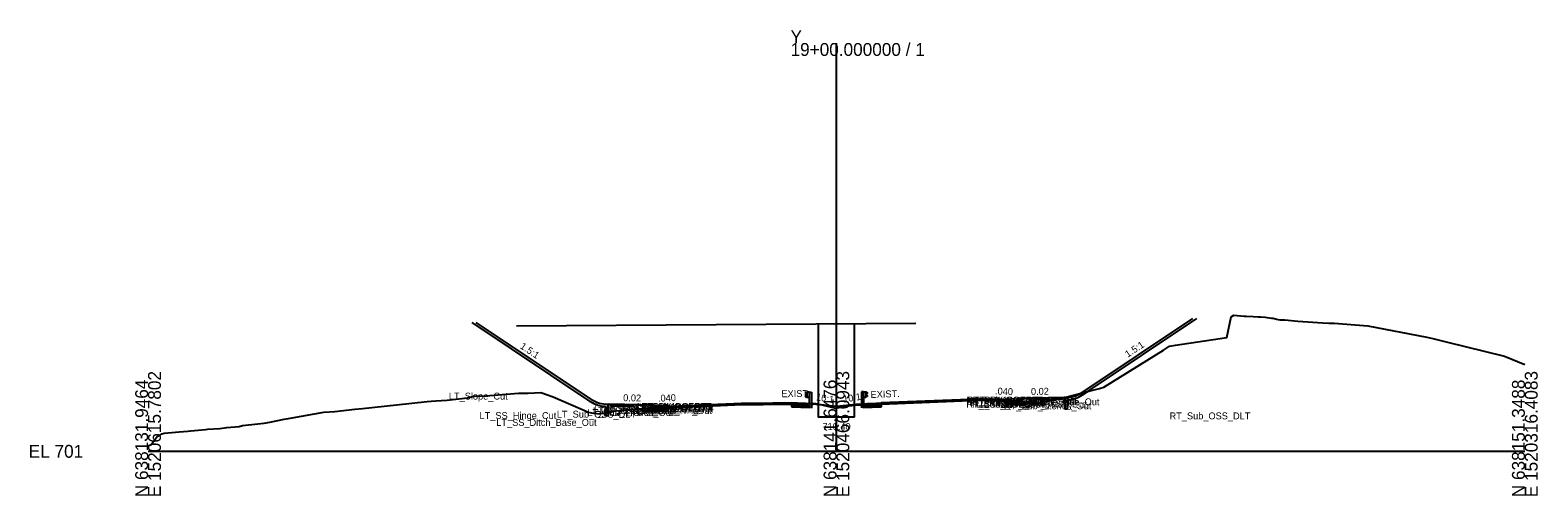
# Model space of a CAD drawing. Extents: x -26 to 303, y -10 to 5039.
# Drawn here: x -25.7 to 302.8, y 2490.3 to 2591.7 of the extents above; entities that cross this region are included whole.
import ezdxf

# ---------------------------------------------------------------- set-up
doc = ezdxf.new("R2010")
doc.units = 0
for name, color, linetype in [('Default', 7, 'Continuous'), ('Exist Cross Section Cell', 7, 'Continuous'), ('Exist XS Center Line Elevation Label', 7, 'Continuous'), ('Exist XS Ground Line', 7, 'Continuous'), ('Prop CMT Bridge Metal Rail', 7, 'Continuous'), ('Prop CMT Pvmt Course 1', 7, 'Continuous'), ('Prop CMT Pvmt Course 2', 7, 'Continuous'), ('Prop CMT Pvmt Course 3', 7, 'Continuous'), ('Prop CMT Pvmt Surface Shoulder', 7, 'Continuous'), ('Prop CMT Shld Paved Course 1', 7, 'Continuous'), ('Prop CMT Shld Paved Course 2', 7, 'Continuous'), ('Prop CMT Shld Paved Course 3', 7, 'Continuous'), ('Prop CMT Slope Grass', 7, 'Continuous'), ('Prop CMT Subgrade Earthwork', 7, 'Continuous'), ('Prop Conc 4in Sidewalk', 7, 'Continuous'), ('Prop XS Earthwork Shape', 7, 'Continuous'), ('Prop XS SE Text', 7, 'Continuous'), ('Prop XS Side Slope Text', 7, 'Continuous'), ('Scratch_Level_0', 7, 'Continuous'), ('Scratch_Level_1', 7, 'Continuous'), ('Typical Curb CELL', 7, 'Continuous'), ('Typical Guardrail CELL', 7, 'Continuous'), ('Typical Shoulder Slope Information CELL', 7, 'Continuous')]:
    doc.layers.add(name, color=color, linetype=linetype)

# ---------------------------------------------------------------- blocks, each defined once
blk = doc.blocks.new('2_6 CURB RIGHT')
at = {"layer": 'Typical Curb CELL'}
for p, q in [((0, -0.58), (0, 0)), ((0, 0), (1.75, -0.07)), ((2, 0.17), (2, 0.18)), ((2.5, 0.42), (2.24, 0.42)), ((2.31, 0.08), (2.33, -0.01)), ((2.46, 0.04), (2.31, 0.08)), ((2.33, -0.01), (2.46, 0.04)), ((2.5, -0.58), (2.5, 0.42)), ((2.5, -0.58), (0, -0.58)), ((0.26, -0.34), (0.35, -0.22)), ((0.38, -0.34), (0.26, -0.34)), ((0.35, -0.22), (0.38, -0.34)), ((1.03, -0.39), (1.09, -0.28)), ((1.19, -0.36), (1.03, -0.39)), ((1.09, -0.28), (1.19, -0.36)), ((1.51, -0.34), (1.6, -0.22)), ((1.63, -0.34), (1.51, -0.34)), ((1.6, -0.22), (1.63, -0.34)), ((2.27, -0.39), (2.34, -0.28)), ((2.44, -0.36), (2.27, -0.39)), ((2.34, -0.28), (2.44, -0.36))]:
    blk.add_line(p, q, dxfattribs=at)
for centre in [(2.27, 0.34), (2.43, 0.12), (2.49, 0.31), (0.01, -0.55), (0.02, -0.25), (0.03, -0.15), (0.07, -0.39), (0.09, -0.18), (0.17, -0.34), (0.2, -0.06), (0.22, -0.58), (0.3, -0.14), (0.34, -0.04), (0.38, -0.51), (0.49, -0.1), (0.52, -0.21), (0.59, -0.53), (0.67, -0.29), (0.69, -0.12), (0.7, -0.45), (0.71, -0.07), (0.76, -0.56), (0.79, -0.26), (0.93, -0.5), (0.97, -0.1), (1.09, -0.15), (1.11, -0.54), (1.26, -0.55), (1.27, -0.25), (1.28, -0.15), (1.32, -0.39), (1.34, -0.18), (1.42, -0.34), (1.45, -0.1), (1.47, -0.58), (1.54, -0.14), (1.63, -0.51), (1.74, -0.1), (1.77, -0.21), (1.84, -0.53), (1.92, -0.29), (1.94, -0.12), (1.95, -0.45), (1.96, -0.07), (2.01, -0.56), (2.04, -0.26), (2.18, -0.5), (2.22, -0.1), (2.34, -0.15), (2.35, -0.54)]:
    blk.add_circle(centre, 0.00802, dxfattribs=at)
for centre, start, end in [((1.76, 0.17), 267.6155, 0), ((2.24, 0.18), 90, 180)]:
    blk.add_arc(centre, 0.24, start, end, dxfattribs=at)

msp = doc.modelspace()

# ---------------------------------------------------------------- linework, layer by layer
at = {"layer": 'Exist Cross Section Cell'}
for p, q in [((150, 2500), (150, 2588.88)), ((0, 2500), (150, 2500)), ((150, 2500), (300, 2500))]:
    msp.add_line(p, q, dxfattribs=at)
at = {"layer": 'Exist XS Ground Line'}
msp.add_lwpolyline([(0, 2501.16), (0.7, 2501.5), (2.01, 2503.24), (2.64, 2503.53), (3.02, 2503.8), (3.52, 2503.95), (5.99, 2504.17), (6.79, 2504.21), (8.64, 2504.35), (9.32, 2504.44), (12.49, 2504.74), (12.98, 2504.8), (15.63, 2504.94), (17.13, 2505.15), (19.83, 2505.39), (20.59, 2505.59), (23.92, 2505.97), (25.3, 2506.15), (26.56, 2506.33), (29.68, 2507.03), (31.37, 2507.27), (38.28, 2508.49), (40.73, 2508.7), (45.04, 2509.14), (46.76, 2509.29), (54.1, 2510.12), (60.8, 2510.87), (61.71, 2510.9), (62.71, 2510.98), (65.17, 2511.14), (69.63, 2511.67), (70.88, 2511.98), (73.59, 2512.09), (80.7, 2512.68), (82.85, 2512.64), (85.59, 2512.79), (88.24, 2511.86), (95.95, 2508.51), (96.61, 2508.37), (98.4, 2508.14), (101.94, 2508.81), (107.02, 2509.27), (110.46, 2509.52), (110.77, 2509.54), (112.13, 2509.61), (112.95, 2509.67), (114.15, 2509.75), (114.51, 2509.75), (116.45, 2509.85), (117.15, 2509.88), (119.77, 2510.01), (121.55, 2510.11), (122.16, 2510.14), (124.76, 2510.26), (125.89, 2510.33), (127.14, 2510.35), (129.14, 2510.38), (129.63, 2510.39), (131.5, 2510.41), (132.16, 2510.42), (132.89, 2510.43), (134.66, 2510.46), (135.53, 2510.47), (137.06, 2510.48), (138.08, 2510.51), (141.53, 2510.46), (145.46, 2510.38), (147.5, 2509.99), (149.82, 2509.37), (152.24, 2509.8), (154.42, 2510.08), (158.72, 2510.33), (162.26, 2510.58), (162.88, 2510.59), (164.76, 2510.65), (165.06, 2510.66), (167.26, 2510.74), (169.18, 2510.81), (169.76, 2510.83), (170.42, 2510.86), (172.26, 2510.92), (173.17, 2510.96), (174.1, 2511), (174.75, 2511), (175.76, 2511.02), (177.25, 2511.06), (178.44, 2511.08), (179.75, 2511.11), (180.9, 2511.13), (182.25, 2511.15), (183.76, 2511.17), (184.74, 2511.18), (185.05, 2511.17), (185.41, 2511.16), (185.87, 2511.15), (187.3, 2511.05), (190.09, 2510.87), (192.06, 2510.44), (192.93, 2510.26), (196.43, 2511.01), (199.73, 2511.7), (205.01, 2513.12), (207.33, 2513.65), (208.26, 2513.99), (221.25, 2521.99), (222.61, 2522.89), (223.91, 2523.09), (235.08, 2524.77), (236.02, 2529.27), (236.59, 2529.63), (238.88, 2529.39), (239.31, 2529.43), (240.83, 2529.34), (241.89, 2529.3), (242.43, 2529.3), (243.43, 2529.23), (244.81, 2529.02), (245.15, 2528.97), (245.87, 2528.78), (246.64, 2528.63), (247.69, 2528.61), (250.57, 2528.31), (256.02, 2527.96), (257.27, 2527.91), (258.49, 2527.86), (265.8, 2527.35), (278.68, 2524.84), (279.96, 2524.57), (282.83, 2523.85), (295.54, 2520.74), (300, 2518.91)], dxfattribs=at)
at = {"layer": 'Prop CMT Bridge Metal Rail'}
for p, q in [((96.36, 2510.86), (70.63, 2528.02)), ((96.64, 2511.28), (71.52, 2528.02)), ((167.28, 2527.82), (80.27, 2527.26)), ((153.92, 2507.41), (153.92, 2527.73)), ((203.32, 2512.66), (227.65, 2528.88)), ((204.83, 2513.07), (228.56, 2528.89)), ((100.24, 2510.27), (100.24, 2507.77)), ((100.25, 2510.27), (100.25, 2507.77)), ((199.75, 2511.68), (199.65, 2511.68)), ((199.75, 2511.68), (199.75, 2509.18)), ((200.25, 2511.18), (200.25, 2509.18)), ((203.64, 2512.28), (204.83, 2513.07)), ((99.75, 2509.77), (99.75, 2507.77)), ((99.75, 2507.77), (100.24, 2507.77)), ((200.25, 2509.18), (199.75, 2509.18))]:
    msp.add_line(p, q, dxfattribs=at)
msp.add_lwpolyline([(153.92, 2507.41), (146.08, 2507.41), (146.08, 2527.68)], dxfattribs=at)
for centre, radius, start, end in [((99.98, 2516.26), 6.5, 236.1329, 267.9819), ((99.98, 2516.26), 6, 236.1329, 272.5897), ((200.02, 2517.68), 6, 267.4103, 303.3375), ((200.02, 2517.68), 6.5, 272.0181, 303.8602)]:
    msp.add_arc(centre, radius, start, end, dxfattribs=at)
at = {"layer": 'Prop CMT Pvmt Course 1'}
for points in [[(140.25, 2510.29), (140.25, 2510.54)], [(159.73, 2510.29), (159.73, 2510.54)], [(186.74, 2510.87), (186.74, 2511.12)], [(113.26, 2509.45), (113.26, 2509.7)]]:
    msp.add_lwpolyline(points, dxfattribs=at)
at = {"layer": 'Prop CMT Pvmt Course 2'}
for points in [[(140.25, 2510.04), (140.25, 2510.29)], [(159.73, 2510.04), (159.73, 2510.29)]]:
    msp.add_lwpolyline(points, dxfattribs=at)
at = {"layer": 'Prop CMT Pvmt Course 3'}
for points in [[(140.25, 2509.66), (140.25, 2510.04)], [(159.73, 2509.66), (159.73, 2510.04)], [(140.26, 2509.66), (140.25, 2509.66)], [(159.72, 2509.66), (159.73, 2509.66)]]:
    msp.add_lwpolyline(points, dxfattribs=at)
at = {"layer": 'Prop CMT Pvmt Surface Shoulder'}
msp.add_line((140.25, 2510.54), (143.24, 2510.43), dxfattribs=at)
for points in [[(127.86, 2510.36), (112.25, 2509.66)], [(140.25, 2510.54), (127.86, 2510.36)], [(156.74, 2510.43), (180.9, 2511.35)], [(180.9, 2511.35), (187.75, 2511.07)]]:
    msp.add_lwpolyline(points, dxfattribs=at)
at = {"layer": 'Prop CMT Shld Paved Course 1'}
for p, q in [((143.51, 2510.16), (143.24, 2510.43)), ((156.47, 2510.16), (156.74, 2510.43)), ((159.73, 2510.29), (180.98, 2511.1))]:
    msp.add_line(p, q, dxfattribs=at)
for points in [[(112.25, 2509.41), (127.87, 2510.11)], [(127.87, 2510.11), (140.25, 2510.29)], [(187.75, 2510.82), (180.98, 2511.1)], [(187.75, 2510.82), (186.74, 2510.87)], [(112.25, 2509.41), (113.26, 2509.45)]]:
    msp.add_lwpolyline(points, dxfattribs=at)
at = {"layer": 'Prop CMT Shld Paved Course 2'}
for p, q in [((143.77, 2509.9), (143.51, 2510.16)), ((156.21, 2509.9), (156.47, 2510.16))]:
    msp.add_line(p, q, dxfattribs=at)
for points in [[(140.25, 2510.29), (143.51, 2510.16)], [(143.77, 2509.9), (140.25, 2510.04)], [(156.21, 2509.9), (159.73, 2510.04)], [(159.73, 2510.29), (156.47, 2510.16)], [(186.74, 2510.87), (187.75, 2510.82)], [(187.75, 2510.57), (186.74, 2510.62)], [(113.26, 2509.45), (112.25, 2509.41)], [(112.25, 2509.16), (113.26, 2509.2)]]:
    msp.add_lwpolyline(points, dxfattribs=at)
at = {"layer": 'Prop CMT Shld Paved Course 3'}
for p, q in [((190.25, 2510.49), (190.75, 2510.49)), ((190.75, 2510.49), (191.18, 2510.06)), ((109.25, 2509.08), (108.82, 2508.65)), ((109.75, 2509.08), (109.25, 2509.08)), ((144.16, 2509.51), (143.77, 2509.9)), ((155.81, 2509.51), (156.21, 2509.9))]:
    msp.add_line(p, q, dxfattribs=at)
for points in [[(140.25, 2510.04), (143.77, 2509.9)], [(159.73, 2510.04), (156.21, 2509.9)], [(186.74, 2510.62), (187.75, 2510.57)], [(191.18, 2510.06), (186.74, 2510.24)], [(108.82, 2508.65), (113.26, 2508.83)], [(113.26, 2509.2), (112.25, 2509.16)], [(144.16, 2509.51), (140.25, 2509.66)], [(155.81, 2509.51), (159.73, 2509.66)]]:
    msp.add_lwpolyline(points, dxfattribs=at)
at = {"layer": 'Prop CMT Slope Grass'}
for p, q in [((100.25, 2510.27), (109.75, 2510.08)), ((149.99, 2509.75), (143.24, 2510.43)), ((149.99, 2509.75), (156.74, 2510.43)), ((199.65, 2511.68), (190.25, 2511.49))]:
    msp.add_line(p, q, dxfattribs=at)
at = {"layer": 'Prop CMT Subgrade Earthwork'}
for p, q in [((108.82, 2508.65), (107.35, 2510.13)), ((140.25, 2510.54), (140.25, 2509.66)), ((144.16, 2509.51), (144.92, 2510.26)), ((155.81, 2509.51), (155.06, 2510.26)), ((159.73, 2510.54), (159.73, 2509.66)), ((186.74, 2510.24), (186.74, 2511.12)), ((187.75, 2510.49), (187.75, 2511.07)), ((190.25, 2510.49), (187.75, 2510.49)), ((190.25, 2510.49), (190.25, 2511.49)), ((191.18, 2510.06), (192.65, 2511.54)), ((113.26, 2508.83), (113.26, 2509.7))]:
    msp.add_line(p, q, dxfattribs=at)
for points in [[(100.25, 2508.49), (100.25, 2510.27)], [(140.25, 2510.54), (140.25, 2509.66), (140.26, 2509.66)], [(159.73, 2510.54), (159.73, 2509.66), (159.72, 2509.66)], [(186.74, 2510.24), (191.18, 2510.06)], [(113.26, 2508.83), (108.82, 2508.65)], [(140.25, 2509.66), (144.16, 2509.51)], [(159.73, 2509.66), (155.81, 2509.51)]]:
    msp.add_lwpolyline(points, dxfattribs=at)
at = {"layer": 'Prop Conc 4in Sidewalk'}
for p, q in [((100.74, 2510.26), (100.74, 2509.92)), ((105.74, 2510.16), (105.74, 2509.82)), ((194.25, 2511.57), (194.25, 2511.24)), ((199.25, 2511.34), (194.25, 2511.24)), ((199.25, 2511.67), (199.25, 2511.34)), ((100.74, 2509.92), (105.74, 2509.82))]:
    msp.add_line(p, q, dxfattribs=at)
at = {"layer": 'Prop XS Earthwork Shape'}
for points in [[(101.94, 2508.81), (107.02, 2509.27), (108.12, 2509.35), (107.35, 2510.13), (100.25, 2510.27), (100.25, 2508.49)], [(124.76, 2510.26), (125.89, 2510.33), (127.14, 2510.35), (127.67, 2510.35), (117.29, 2509.88), (119.77, 2510.01), (121.55, 2510.11), (122.16, 2510.14)], [(127.67, 2510.35), (129.14, 2510.38), (129.25, 2510.38), (127.86, 2510.36)], [(129.25, 2510.38), (129.63, 2510.39), (131.5, 2510.41), (132.16, 2510.42)], [(135.53, 2510.47), (137.06, 2510.48), (138.08, 2510.51), (132.16, 2510.42), (132.89, 2510.43), (134.66, 2510.46)], [(140.25, 2510.54), (140.25, 2510.48), (138.08, 2510.51)], [(144.16, 2509.51), (144.92, 2510.26), (143.3, 2510.42), (141.53, 2510.46), (140.25, 2510.48), (140.26, 2509.66)], [(144.92, 2510.26), (143.3, 2510.42), (145.46, 2510.38), (147.35, 2510.02)], [(147.35, 2510.02), (147.5, 2509.99), (149.82, 2509.37), (152.24, 2509.8), (154.42, 2510.08), (155.2, 2510.12), (155.06, 2510.26), (149.99, 2509.75)], [(155.2, 2510.12), (158.72, 2510.33), (159.73, 2510.4), (159.72, 2509.66), (155.81, 2509.51)], [(185.05, 2511.17), (185.41, 2511.16), (185.62, 2511.16), (180.9, 2511.35), (159.73, 2510.54), (159.73, 2510.4), (162.26, 2510.58), (162.88, 2510.59), (164.76, 2510.65), (165.06, 2510.66), (167.26, 2510.74), (169.18, 2510.81), (169.76, 2510.83), (170.42, 2510.86), (172.26, 2510.92), (173.17, 2510.96), (174.1, 2511), (174.75, 2511), (175.76, 2511.02), (177.25, 2511.06), (178.44, 2511.08), (179.75, 2511.11), (180.9, 2511.13), (182.25, 2511.15), (183.76, 2511.17), (184.74, 2511.18)], [(185.62, 2511.16), (185.87, 2511.15), (186, 2511.14)], [(186.74, 2511.09), (186.74, 2511.12), (186, 2511.14)], [(187.3, 2511.05), (187.75, 2511.02), (187.75, 2510.49), (190.25, 2510.49), (190.25, 2510.83), (191.65, 2510.53), (191.18, 2510.06), (186.74, 2510.24), (186.74, 2511.09)], [(187.75, 2511.02), (190.09, 2510.87), (190.25, 2510.83), (190.25, 2510.49), (187.75, 2510.49)], [(199.65, 2511.68), (192.65, 2511.54), (191.65, 2510.53), (192.06, 2510.44), (192.93, 2510.26), (196.43, 2511.01)], [(112.95, 2509.67), (113.26, 2509.69), (113.26, 2508.83), (108.82, 2508.65), (108.12, 2509.35), (110.46, 2509.52), (110.77, 2509.54), (112.13, 2509.61)], [(113.26, 2509.69), (114, 2509.74), (113.26, 2509.7)], [(114.15, 2509.75), (114.23, 2509.75), (114, 2509.74)], [(114.51, 2509.75), (116.45, 2509.85), (114.23, 2509.75)], [(117.29, 2509.88), (116.45, 2509.85), (117.15, 2509.88)]]:
    msp.add_lwpolyline(points, close=True, dxfattribs=at)
at = {"layer": 'Scratch_Level_1'}
for p, q in [((150, 2500), (150, 2552.78)), ((132.16, 2510.42), (140.25, 2510.54))]:
    msp.add_line(p, q, dxfattribs=at)
at = {"layer": 'Typical Guardrail CELL'}
for p, q in [((143.57, 2512.89), (143.28, 2512.69)), ((143.57, 2512.36), (143.28, 2512.56)), ((143.57, 2512.27), (143.28, 2512.06)), ((143.57, 2511.73), (143.28, 2511.94)), ((144.07, 2512.89), (143.57, 2512.89)), ((143.57, 2512.89), (143.57, 2511.73)), ((143.57, 2512.31), (143.57, 2512.36)), ((143.57, 2512.31), (143.57, 2512.27)), ((144.07, 2511.73), (143.57, 2511.73)), ((144.07, 2512.89), (144.07, 2510.41)), ((144.07, 2512.89), (144.57, 2512.89)), ((144.07, 2510.41), (144.57, 2510.41)), ((144.07, 2510.41), (144.07, 2509.4)), ((144.57, 2512.89), (144.57, 2510.41)), ((144.57, 2510.41), (144.57, 2509.4)), ((155.93, 2512.93), (155.43, 2512.93)), ((155.43, 2512.93), (155.43, 2510.45)), ((155.93, 2510.45), (155.43, 2510.45)), ((155.43, 2510.45), (155.43, 2509.44)), ((155.93, 2512.93), (155.93, 2510.45)), ((155.93, 2512.93), (156.43, 2512.93)), ((155.93, 2511.77), (156.43, 2511.77)), ((155.93, 2510.45), (155.93, 2509.44)), ((156.43, 2512.93), (156.43, 2511.77)), ((156.43, 2512.93), (156.72, 2512.73)), ((156.43, 2512.4), (156.72, 2512.6)), ((156.43, 2512.35), (156.43, 2512.4)), ((156.43, 2512.35), (156.43, 2512.31)), ((156.43, 2512.31), (156.72, 2512.1)), ((156.43, 2511.77), (156.72, 2511.98))]:
    msp.add_line(p, q, dxfattribs=at)
for centre, start, end in [((143.33, 2512.63), 125.003, 235.0112), ((143.33, 2512), 125.0059, 235.0366), ((156.67, 2512.67), 304.9888, 54.997), ((156.67, 2512.04), 304.9634, 54.9941)]:
    msp.add_arc(centre, 0.0776, start, end, dxfattribs=at)

# ---------------------------------------------------------------- block references
at = {"layer": 'Prop CMT Slope Grass', "yscale": -1, "rotation": 180}
msp.add_blockref('2_6 CURB RIGHT', (112.25, 2509.66), dxfattribs=at)
at = {"layer": 'Prop CMT Slope Grass'}
msp.add_blockref('2_6 CURB RIGHT', (187.75, 2511.07), dxfattribs=at)

# ---------------------------------------------------------------- texts
at = {"layer": 'Default'}
msp.add_text('-', height=0.0001, dxfattribs=at).set_placement((0, 2500))
at = {"layer": 'Exist Cross Section Cell'}
for s, p in [('Y', (140, 2588.88)), ('19+00.000000 / 1', (140, 2586.08)), ('EL 701', (-26, 2498.6))]:
    msp.add_text(s, height=2.8, dxfattribs=at).set_placement(p)
for s, p in [('E 1520615.7802', (2.8, 2490)), ('E 1520466.0943', (152.8, 2490)), ('E 1520316.4083', (302.8, 2490)), ('N 638131.9464', (0, 2490)), ('N 638141.6476', (150, 2490)), ('N 638151.3488', (300, 2490))]:
    msp.add_text(s, height=2.8, rotation=90, dxfattribs=at).set_placement(p)
at = {"layer": 'Exist XS Center Line Elevation Label'}
msp.add_text('710.40', height=1.5, dxfattribs=at).set_placement((146.96, 2504.65))
at = {"layer": 'Prop XS SE Text'}
for s, rotation, p in [('EXIST.', 0.8055, (138.02, 2511.76)), ('EXIST.', 2.1782, (157.46, 2511.6)), ('.040', 357.7094, (184.54, 2512.38)), ('.040', 2.2906, (111.14, 2510.79))]:
    msp.add_text(s, height=1.5, rotation=rotation, dxfattribs=at).set_placement(p)
at = {"layer": 'Prop XS Side Slope Text'}
for s, rotation, p in [('1.5:1', 326.6863, (80.92, 2522.53)), ('1.5:1', 33.3137, (213.49, 2520.37)), ('10:1', 350.5377, (145.49, 2511.13)), ('10:1', 9.4623, (151.59, 2510.58))]:
    msp.add_text(s, height=1.5, rotation=rotation, dxfattribs=at).set_placement(p)
at = {"layer": 'Scratch_Level_0'}
for s, p in [('LT_Slope_Cut', (65.55, 2511.26)), ('LT_GS_OS_CTL', (97.19, 2508.53)), ('LT_PS1_OEOP', (99.85, 2508.62)), ('LT_PV2_PGL_Out', (106.36, 2508.74)), ('LT_PV3_PGL_Out', (106.36, 2508.49)), ('LT_Sub_Out_DLT', (106.49, 2508.99)), ('LT_PV1_PGL_Out', (106.54, 2508.99)), ('LT_PV2_OEOT', (107.61, 2508.74)), ('LT_PV3_OEOT', (107.61, 2508.49)), ('LT_PV1_OEOT', (107.79, 2508.99)), ('RT_PV2_PGL_Out', (178.27, 2510.14)), ('RT_PV3_PGL_Out', (178.27, 2509.89)), ('RT_Sub_PGL_Out', (178.31, 2509.52)), ('RT_Sub_Out_DLT', (178.37, 2510.4)), ('RT_PV1_PGL_Out', (178.45, 2510.39)), ('RT_PV2_OEOT', (179.54, 2510.14)), ('RT_PV3_OEOT', (179.54, 2509.89)), ('RT_Sub_OEOT', (179.57, 2509.52)), ('RT_PV1_OEOT', (179.72, 2510.39)), ('RT_SS_Ditch_Base_Out', (185.13, 2510.02)), ('RT_Sub_Trench_Out', (186.5, 2509.14)), ('RT_PS3_Shelf_Out', (186.93, 2509.53)), ('RT_PS1_OEOP', (187.78, 2510.07)), ('RT_PS2_OEOP', (187.86, 2509.81)), ('RT_PS3_OEOP', (188.12, 2509.55)), ('RT_Slope_Cut', (189.25, 2510.02)), ('LT_SS_Hinge_Cut', (72.23, 2507.03)), ('LT_SS_Ditch_Base_Out', (75.88, 2505.53)), ('LT_Sub_OSS_DLT', (89.06, 2507.33)), ('LT_Sub_Trench_Out', (95.74, 2507.68)), ('LT_PS3_Shelf_Out', (96.95, 2508.08)), ('LT_PS3_OEOP', (99.15, 2508.1)), ('LT_PS2_OEOP', (99.41, 2508.36)), ('LT_Sub_PGL_Out', (106.4, 2508.11)), ('LT_Sub_OEOT', (107.64, 2508.11)), ('RT_Sub_OSS_DLT', (222.59, 2506.96))]:
    msp.add_text(s, height=1.5, dxfattribs=at).set_placement(p)
at = {"layer": 'Typical Shoulder Slope Information CELL'}
for rotation, p in [(1.1403, (192.4, 2512.26)), (358.8597, (103.52, 2510.92))]:
    msp.add_text('0.02', height=1.5, rotation=rotation, dxfattribs=at).set_placement(p)

doc.saveas('drawing.dxf')
